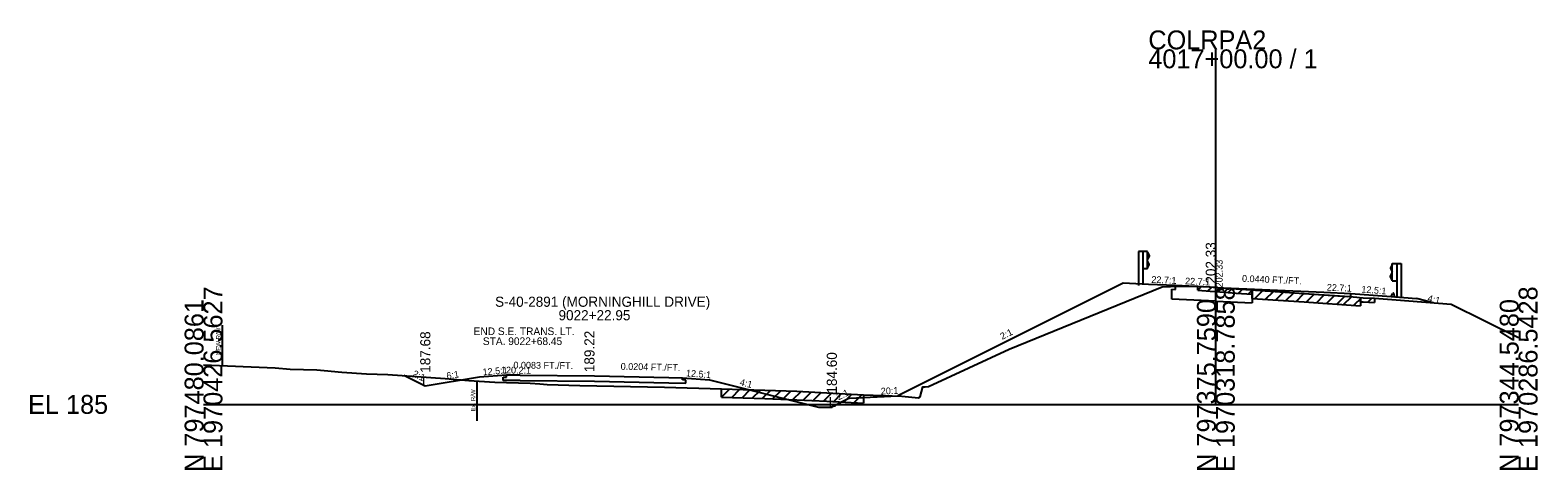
# Model space of a CAD drawing. Extents: x -26 to 1971083, y -10 to 798159.
# Drawn here: x -25.7 to 197.7, y 1490.3 to 1555.4 of the extents above; entities that cross this region are included whole.
import ezdxf

# ---------------------------------------------------------------- set-up
doc = ezdxf.new("R2010")
doc.units = 0
for name, color, linetype in [('RD_GPK_XS_Cell', 7, 'Continuous'), ('RD_XS_Base', 7, 'Continuous'), ('RD_XS_CurbTop', 7, 'Continuous'), ('RD_XS_EarthShd', 7, 'Continuous'), ('RD_XS_ExGround', 7, 'Continuous'), ('RD_XS_ExPaveRet', 7, 'Continuous'), ('RD_XS_ExRW', 7, 'Continuous'), ('RD_XS_GR', 7, 'Continuous'), ('RD_XS_Misc_Line', 7, 'Continuous'), ('RD_XS_NewRW', 7, 'Continuous'), ('RD_XS_Pave', 7, 'Continuous'), ('RD_XS_PaveOvlay', 7, 'Continuous'), ('RD_XS_PaveShd', 7, 'Continuous'), ('RD_XS_TieSlope', 7, 'Continuous'), ('RD_XS_TX_Elev_EX', 7, 'Continuous'), ('RD_XS_TX_Elev_PR', 7, 'Continuous'), ('RD_XS_TX_Misc', 7, 'Continuous'), ('RD_XS_TX_MkPT', 7, 'Continuous'), ('RD_XS_TX_Notes', 7, 'Continuous'), ('RD_XS_TX_Profile', 7, 'Continuous'), ('RD_XS_TX_ShdSlope', 7, 'Continuous'), ('RD_XS_TX_Slope', 7, 'Continuous'), ('RD_XS_TX_Station', 7, 'Continuous')]:
    doc.layers.add(name, color=color, linetype=linetype)

msp = doc.modelspace()

# ---------------------------------------------------------------- linework, layer by layer
at = {"layer": 'RD_GPK_XS_Cell'}
for p, q in [((150, 1500), (150, 1552.59)), ((0, 1500), (150, 1500)), ((150, 1500), (194.87, 1500))]:
    msp.add_line(p, q, dxfattribs=at)
at = {"layer": 'RD_XS_Base'}
for p, q in [((143.5, 1517.06), (144, 1517.04)), ((143.5, 1515.58), (143.5, 1517.06)), ((144, 1517.04), (144, 1517.6)), ((150, 1515.29), (143.5, 1515.58)), ((150, 1515.29), (155.38, 1515.06)), ((170, 1515.95), (170, 1516.45)), ((44.39, 1504.03), (44.9, 1504.03)), ((44.39, 1503.55), (44.39, 1504.03)), ((46.9, 1503.53), (44.39, 1503.55)), ((44.9, 1504.03), (44.9, 1504.33)), ((46.9, 1503.53), (57.93, 1503.44)), ((70.97, 1503.65), (70.97, 1503.95)), ((71.47, 1503.64), (70.97, 1503.65)), ((71.47, 1503.16), (71.47, 1503.64)), ((57.93, 1503.44), (68.97, 1503.21)), ((68.97, 1503.21), (71.47, 1503.16))]:
    msp.add_line(p, q, dxfattribs=at)
at = {"layer": 'RD_XS_CurbTop'}
for p, q in [((176, 1515.97), (176.25, 1516.43)), ((176, 1515.97), (176.47, 1515.94)), ((176.47, 1515.94), (176.41, 1516.37))]:
    msp.add_line(p, q, dxfattribs=at)
msp.add_ellipse((176.32, 1516.35), major_axis=(0, -0.131), ratio=0.686, start_param=1.762783, end_param=4.036677, dxfattribs=at)
at = {"layer": 'RD_XS_EarthShd'}
for p, q in [((144, 1517.6), (140, 1517.77)), ((170, 1516.45), (176, 1515.97)), ((44.9, 1504.33), (40.88, 1504.01)), ((70.97, 1503.95), (74.97, 1503.63))]:
    msp.add_line(p, q, dxfattribs=at)
at = {"layer": 'RD_XS_ExGround'}
msp.add_lwpolyline([(0, 1505.85), (10.62, 1505.41), (12.84, 1505.23), (16.77, 1505.1), (17.89, 1505.03), (20.49, 1504.76), (24.16, 1504.54), (27.29, 1504.44), (35.8, 1503.82), (39.32, 1503.54), (43.15, 1503.3), (48.4, 1503.16), (49.82, 1503.03), (50.93, 1502.96), (55.78, 1502.78), (68.32, 1502.54), (76.77, 1502.33), (83.19, 1502.11), (87.89, 1501.94), (92.34, 1501.71), (97.77, 1501.42), (103.47, 1501.2), (105.96, 1500.95), (106.19, 1501.14), (106.58, 1502.59), (106.91, 1502.61), (107.42, 1502.65), (119.4, 1508.16), (142.05, 1517.43), (144.54, 1517.49), (147.32, 1517.53), (149.16, 1517.4), (150, 1517.33), (153, 1517.12), (163.08, 1516.43), (169.83, 1515.97), (170.91, 1515.87), (171.27, 1515.84), (171.83, 1515.81), (173.53, 1515.72), (176.71, 1515.48), (184.86, 1514.86), (194.87, 1509.92)], dxfattribs=at)
at = {"layer": 'RD_XS_ExPaveRet'}
for p, q in [((147.32, 1516.91), (147.32, 1517.53)), ((155.38, 1515.71), (155.38, 1516.96)), ((155.38, 1516.96), (155.38, 1516.33)), ((147.32, 1516.91), (149.16, 1516.77)), ((149.16, 1516.77), (150, 1516.71)), ((150, 1516.71), (153, 1516.49)), ((153, 1516.49), (155.38, 1516.33)), ((155.38, 1515.71), (163.08, 1515.18)), ((163.08, 1515.18), (171.45, 1514.61)), ((171.45, 1515.83), (171.45, 1514.61)), ((171.45, 1515.21), (171.45, 1515.83)), ((171.45, 1515.21), (171.83, 1515.19)), ((171.83, 1515.19), (173.53, 1515.09)), ((173.53, 1515.72), (173.53, 1515.09)), ((76.77, 1501.08), (76.77, 1502.33)), ((97.77, 1501.42), (97.77, 1500.17)), ((76.77, 1501.08), (83.19, 1500.86)), ((83.19, 1500.86), (87.89, 1500.69)), ((87.89, 1500.69), (92.34, 1500.46)), ((92.34, 1500.46), (97.77, 1500.17))]:
    msp.add_line(p, q, dxfattribs=at)
at = {"layer": 'RD_XS_ExRW'}
msp.add_line((40.52, 1503.55), (40.52, 1497.55), dxfattribs=at)
at = {"layer": 'RD_XS_GR'}
for p, q in [((139.19, 1522.65), (138.52, 1522.65)), ((138.52, 1522.65), (138.52, 1517.6)), ((139.85, 1522.65), (139.19, 1522.65)), ((139.19, 1522.65), (139.19, 1517.71)), ((139.85, 1520.08), (139.85, 1522.65)), ((139.85, 1522.49), (140.12, 1522.05)), ((140.12, 1521.94), (139.85, 1521.5)), ((140.12, 1522.05), (140.12, 1521.94)), ((139.85, 1520.08), (139.19, 1520.08)), ((140.12, 1520.79), (139.85, 1521.23)), ((139.85, 1520.24), (140.12, 1520.68)), ((140.12, 1520.68), (140.12, 1520.79)), ((176.15, 1520.69), (175.88, 1520.25)), ((175.88, 1520.25), (175.88, 1520.14)), ((175.88, 1520.14), (176.15, 1519.7)), ((175.88, 1518.99), (176.15, 1519.43)), ((176.15, 1520.85), (176.81, 1520.85)), ((176.15, 1518.28), (176.15, 1520.85)), ((176.81, 1520.85), (177.48, 1520.85)), ((176.81, 1520.85), (176.81, 1515.91)), ((177.48, 1520.85), (177.48, 1515.8)), ((175.88, 1518.88), (175.88, 1518.99)), ((176.15, 1518.44), (175.88, 1518.88)), ((176.15, 1518.28), (176.81, 1518.28))]:
    msp.add_line(p, q, dxfattribs=at)
at = {"layer": 'RD_XS_Misc_Line'}
for p, q in [((147.32, 1516.91), (147.91, 1517.49)), ((148.83, 1516.8), (149.41, 1517.38)), ((150.33, 1516.69), (150.92, 1517.27)), ((151.84, 1516.58), (152.42, 1517.16)), ((153.34, 1516.47), (153.93, 1517.05)), ((154.85, 1516.37), (155.44, 1516.95)), ((155.77, 1515.68), (156.94, 1516.85)), ((157.36, 1515.57), (158.54, 1516.74)), ((158.87, 1515.47), (160.04, 1516.64)), ((160.38, 1515.37), (161.55, 1516.54)), ((161.88, 1515.26), (163.06, 1516.43)), ((163.39, 1515.16), (164.57, 1516.33)), ((164.9, 1515.06), (166.07, 1516.23)), ((166.41, 1514.95), (167.58, 1516.12)), ((167.91, 1514.85), (169.09, 1516.02)), ((168.93, 1514.78), (170.1, 1515.95)), ((170.46, 1514.68), (171.61, 1515.83)), ((172.53, 1515.15), (173.12, 1515.74)), ((76.77, 1501.08), (77.99, 1502.29)), ((78.28, 1501.03), (79.49, 1502.24)), ((79.79, 1500.98), (81, 1502.19)), ((81.3, 1500.93), (82.51, 1502.13)), ((82.8, 1500.87), (84.02, 1502.08)), ((84.31, 1500.82), (85.52, 1502.03)), ((85.82, 1500.77), (87.03, 1501.97)), ((87.33, 1500.71), (88.53, 1501.91)), ((88.83, 1500.64), (90.03, 1501.83)), ((90.34, 1500.56), (91.53, 1501.75)), ((91.85, 1500.48), (93.04, 1501.67)), ((93.36, 1500.4), (94.55, 1501.59)), ((94.86, 1500.32), (96.06, 1501.51)), ((96.37, 1500.24), (97.56, 1501.43))]:
    msp.add_line(p, q, dxfattribs=at)
at = {"layer": 'RD_XS_NewRW'}
msp.add_line((2.77, 1511.73), (2.77, 1505.73), dxfattribs=at)
at = {"layer": 'RD_XS_Pave'}
for p, q in [((150, 1517.33), (166, 1516.63)), ((46.9, 1504.31), (57.93, 1504.22)), ((57.93, 1504.22), (68.97, 1503.99))]:
    msp.add_line(p, q, dxfattribs=at)
at = {"layer": 'RD_XS_PaveOvlay'}
for p, q in [((155.38, 1516.96), (155.38, 1515.06)), ((157.36, 1516.82), (163.08, 1516.43)), ((163.08, 1516.43), (169.52, 1515.99))]:
    msp.add_line(p, q, dxfattribs=at)
at = {"layer": 'RD_XS_PaveShd'}
for p, q in [((150, 1517.33), (144, 1517.6)), ((166, 1516.63), (170, 1516.45)), ((46.9, 1504.31), (44.9, 1504.33)), ((68.97, 1503.99), (70.97, 1503.95))]:
    msp.add_line(p, q, dxfattribs=at)
at = {"layer": 'RD_XS_TieSlope'}
for p, q in [((136.25, 1517.94), (102.9, 1501.27)), ((140, 1517.77), (136.25, 1517.94)), ((176, 1515.97), (179.75, 1515.67)), ((182.21, 1515.06), (179.75, 1515.67)), ((32.86, 1502.68), (29.68, 1504.26)), ((40.88, 1504.01), (32.86, 1502.68)), ((74.97, 1503.63), (91.1, 1499.6)), ((91.1, 1499.6), (93.16, 1499.6)), ((95.72, 1500.91), (93.1, 1499.6)), ((95.72, 1500.91), (102.9, 1501.27))]:
    msp.add_line(p, q, dxfattribs=at)

# ---------------------------------------------------------------- texts
at = {"layer": 'RD_GPK_XS_Cell'}
for s, p in [('COLRPA2', (140, 1552.59)), ('4017+00.00 / 1', (140, 1549.79)), ('EL 185', (-26, 1498.6))]:
    msp.add_text(s, height=2.8, dxfattribs=at).set_placement(p)
for s, p in [('E 1970426.5627', (2.8, 1490)), ('E 1970318.7858', (152.8, 1490)), ('E 1970286.5428', (197.67, 1490)), ('N 797480.0861', (0, 1490)), ('N 797375.7590', (150, 1490)), ('N 797344.5480', (194.87, 1490))]:
    msp.add_text(s, height=2.8, rotation=90, dxfattribs=at).set_placement(p)
at = {"layer": 'RD_XS_ExRW'}
msp.add_text('Ex. R/W ', height=0.65, rotation=90, dxfattribs=at).set_placement((40.27, 1498.94))
at = {"layer": 'RD_XS_NewRW'}
msp.add_text('NEW R/W ', height=0.65, rotation=90, dxfattribs=at).set_placement((2.51, 1507.29))
at = {"layer": 'RD_XS_TX_Elev_EX'}
msp.add_text('202.33', height=1, rotation=90, dxfattribs=at).set_placement((151, 1517.33))
at = {"layer": 'RD_XS_TX_Elev_PR'}
for s, p in [(' 202.33', (150, 1517.33)), (' 189.22', (57.93, 1504.22))]:
    msp.add_text(s, height=1.5, rotation=90, dxfattribs=at).set_placement(p)
at = {"layer": 'RD_XS_TX_Misc'}
for s, p in [('187.68', (33.61, 1504.68)), ('184.60', (93.85, 1501.6))]:
    msp.add_text(s, height=1.5, rotation=90, dxfattribs=at).set_placement(p)
at = {"layer": 'RD_XS_TX_MkPT'}
for p in [(32.36, 1502.68), (92.6, 1499.6)]:
    msp.add_text('L', height=1.5, dxfattribs=at).set_placement(p)
at = {"layer": 'RD_XS_TX_Notes'}
for s, p in [('END S.E. TRANS. LT. ', (40.02, 1510.27)), ('STA. 9022+68.45', (41.39, 1508.8))]:
    msp.add_text(s, height=1.125, dxfattribs=at).set_placement(p)
at = {"layer": 'RD_XS_TX_Profile'}
msp.add_text('120.2:1', height=1, rotation=359.5234, dxfattribs=at).set_placement((44.07, 1504.59))
at = {"layer": 'RD_XS_TX_ShdSlope'}
for s, rotation, p in [('22.7:1', 357.4806, (140.43, 1518.01)), ('12.5:1', 355.4261, (171.54, 1516.58)), ('12.5:1', 4.5605, (41.39, 1504.3)), ('12.5:1', 355.4323, (71.46, 1504.16))]:
    msp.add_text(s, height=1, rotation=rotation, dxfattribs=at).set_placement(p)
at = {"layer": 'RD_XS_TX_Slope'}
for s, rotation, p in [('0.0440 FT./FT.', 357.4806, (153.86, 1518.17)), ('22.7:1', 357.4806, (145.43, 1517.79)), ('22.7:1', 357.4806, (166.43, 1516.86)), ('4:1', 345.9638, (181.3, 1515.29)), ('2:1', 26.5651, (118.35, 1509.55)), ('0.0083 FT./FT.', 359.5234, (45.91, 1505.32)), ('0.0204 FT./FT.', 358.8286, (61.8, 1505.14)), ('2:1', 333.5023, (30.86, 1504.23)), ('6:1', 9.435, (36.09, 1503.72)), ('4:1', 345.971, (79.37, 1502.85)), ('2:1', 26.5651, (94.1, 1500.59)), ('20:1', 2.8624, (100.38, 1501.45))]:
    msp.add_text(s, height=1, rotation=rotation, dxfattribs=at).set_placement(p)
at = {"layer": 'RD_XS_TX_Station'}
for s, p in [('S-40-2891 (MORNINGHILL DRIVE)', (43.2, 1514.46)), ('9022+22.95', (52.6, 1512.46))]:
    msp.add_text(s, height=1.5, dxfattribs=at).set_placement(p)

doc.saveas('drawing.dxf')
